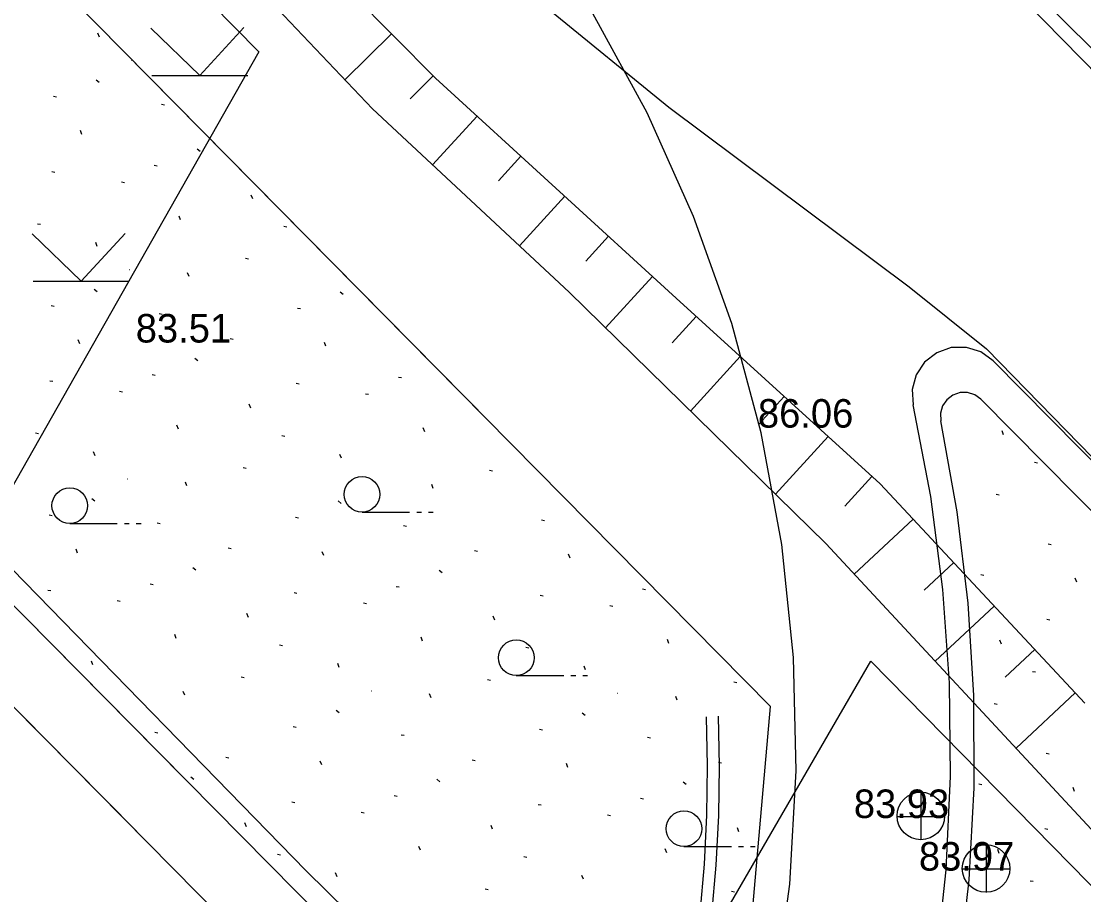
# Model space of a CAD drawing. Extents: x 412225 to 413380, y 4456471 to 4457189.
# Drawn here: x 412488.1 to 412532.83, y 4456813.88 to 4456850.62 of the extents above; entities that cross this region are included whole.
import ezdxf

# ---------------------------------------------------------------- set-up
doc = ezdxf.new("R2010")
doc.units = 0
for name, color, linetype in [('0_HALİHAZIR', 7, 'Continuous'), ('0_KADASTRO', 7, 'Continuous'), ('ADA_KOCEPHE', 7, 'Continuous'), ('ADA_ONCEPHE', 7, 'Continuous'), ('KALDIRIM', 7, 'Continuous'), ('Level 41', 7, 'Continuous'), ('Level 62', 7, 'Continuous')]:
    doc.layers.add(name, color=color, linetype=linetype)

msp = doc.modelspace()

# ---------------------------------------------------------------- linework, layer by layer
at = {"layer": '0_HALİHAZIR'}
for p, q in [((412495.622, 4456848.349), (412493.562, 4456850.339)), ((412495.622, 4456848.349), (412497.472, 4456850.358)), ((412503.688, 4456850.102), (412501.73, 4456848.159)), ((412493.602, 4456848.349), (412497.642, 4456848.348)), ((412505.449, 4456848.327), (412504.468, 4456847.354)), ((412507.29, 4456846.636), (412505.415, 4456844.584)), ((412509.135, 4456844.95), (412508.19, 4456843.915)), ((412510.981, 4456843.264), (412509.073, 4456841.175)), ((412490.621, 4456839.689), (412488.561, 4456841.679)), ((412490.621, 4456839.689), (412492.471, 4456841.699)), ((412512.827, 4456841.577), (412511.864, 4456840.524)), ((412514.673, 4456839.891), (412512.696, 4456837.727)), ((412488.601, 4456839.689), (412492.641, 4456839.689)), ((412516.52, 4456838.206), (412515.503, 4456837.09)), ((412518.368, 4456836.523), (412516.275, 4456834.224)), ((412520.216, 4456834.84), (412519.14, 4456833.657)), ((412522.065, 4456833.156), (412519.851, 4456830.725)), ((412523.913, 4456831.473), (412522.776, 4456830.224)), ((412502.448, 4456829.971), (412504.448, 4456829.971)), ((412504.748, 4456829.971), (412504.948, 4456829.971)), ((412505.248, 4456829.971), (412505.448, 4456829.971)), ((412490.144, 4456829.495), (412492.144, 4456829.495)), ((412492.444, 4456829.495), (412492.644, 4456829.495)), ((412492.944, 4456829.495), (412493.144, 4456829.495)), ((412525.646, 4456829.673), (412523.17, 4456827.361)), ((412527.352, 4456827.846), (412526.113, 4456826.688)), ((412529.059, 4456826.018), (412526.575, 4456823.699)), ((412530.765, 4456824.191), (412529.521, 4456823.03)), ((412508.942, 4456823.097), (412510.942, 4456823.097)), ((412511.242, 4456823.097), (412511.442, 4456823.097)), ((412511.742, 4456823.097), (412511.942, 4456823.097)), ((412532.471, 4456822.364), (412529.98, 4456820.038)), ((412525.989, 4456816.183), (412525.989, 4456818.183)), ((412524.969, 4456817.173), (412526.969, 4456817.173)), ((412516, 4456815.903), (412518, 4456815.902)), ((412518.3, 4456815.902), (412518.5, 4456815.902)), ((412518.8, 4456815.902), (412519, 4456815.902)), ((412528.734, 4456813.971), (412528.734, 4456815.971)), ((412527.714, 4456814.962), (412529.714, 4456814.961))]:
    msp.add_line(p, q, dxfattribs=at)
for points in [[(412283.985, 4457100.322), (412303.353, 4457080.961), (412332.911, 4457051.149), (412362.488, 4457021.336), (412400.253, 4456983.455), (412425.306, 4456957.949), (412451.956, 4456931.175), (412483.613, 4456899.459), (412507.045, 4456875.463), (412533.953, 4456848.693), (412570.746, 4456810.938), (412594.382, 4456786.967), (412618.72, 4456762.275), (412633.267, 4456747.178), (412636.335, 4456744.215)], [(412635.095, 4456744.706), (412621.293, 4456758.968), (412594.514, 4456786.189), (412564.28, 4456816.959), (412527.989, 4456853.886), (412497.963, 4456883.985), (412468.818, 4456913.357), (412423.738, 4456958.933), (412408.728, 4456974.086)], [(412461.571, 4456883.628), (412465.366, 4456883.75), (412468.462, 4456882.217), (412474.258, 4456878.127), (412489.749, 4456864.153), (412505.547, 4456848.228), (412515.676, 4456838.974), (412524.256, 4456831.161), (412532.872, 4456821.935)], [(412533.164, 4456816.614), (412521.975, 4456828.646), (412511.169, 4456839.221), (412502.887, 4456846.939), (412494.891, 4456855.369), (412485.404, 4456864.533), (412471.618, 4456876.544), (412465.786, 4456880.863), (412463.181, 4456882.534), (412461.571, 4456883.628)], [(412532.886, 4456773.972), (412532.31, 4456774.062), (412531.793, 4456774.564), (412531.273, 4456775.296), (412528.663, 4456779.548), (412524.693, 4456785.735), (412521.094, 4456791.304), (412516.782, 4456797.322), (412512.918, 4456801.901), (412508.059, 4456807.056), (412500.088, 4456814.895), (412487.722, 4456827.567), (412472.464, 4456842.514), (412454.647, 4456860.416), (412450.212, 4456864.756)], [(412505.182, 4456855.321), (412515.363, 4456847.006), (412525.484, 4456839.445), (412528.743, 4456836.847), (412540.992, 4456824.288)]]:
    msp.add_lwpolyline(points, dxfattribs=at)
for centre, radius in [((412502.448, 4456830.721), 0.75), ((412490.144, 4456830.245), 0.75), ((412508.942, 4456823.847), 0.75), ((412525.974, 4456817.191), 1), ((412516, 4456816.653), 0.75), ((412528.719, 4456814.98), 1)]:
    msp.add_circle(centre, radius, dxfattribs=at)
at = {"layer": '0_KADASTRO'}
msp.add_lwpolyline([(412245.621, 4457084.985), (412262.788, 4457087.767), (412498.109, 4456849.333), (412486.377, 4456828.685), (412245.456, 4457070.818)], dxfattribs=at)
msp.add_lwpolyline([(412511.64, 4456802.61), (412523.869, 4456823.705), (412617.056, 4456728.859), (412543.593, 4456703.12), (412527.466, 4456778.138), (412524.42, 4456784.89), (412522.24, 4456788.56), (412519.52, 4456792.85), (412512.99, 4456801.24)], close=True, dxfattribs=at)
at = {"layer": 'ADA_KOCEPHE'}
for p, q in [((412299.933, 4457044.174), (412519.643, 4456821.8)), ((412299.933, 4457044.174), (412507.885, 4456833.7)), ((412494.937, 4456818.806), (412285.694, 4457030.12)), ((412511.712, 4456801.864), (412285.694, 4457030.12))]:
    msp.add_line(p, q, dxfattribs=at)
at = {"layer": 'ADA_ONCEPHE'}
for p, q in [((412517.496, 4456819.294), (412517.449, 4456821.382)), ((412518.104, 4456804.245), (412519.643, 4456821.8)), ((412516.996, 4456819.292), (412516.95, 4456821.362)), ((412516.966, 4456817.222), (412516.996, 4456819.292)), ((412517.466, 4456817.206), (412517.496, 4456819.294)), ((412516.86, 4456815.155), (412516.966, 4456817.222)), ((412517.359, 4456815.12), (412517.466, 4456817.206)), ((412516.677, 4456813.093), (412516.86, 4456815.155)), ((412517.174, 4456813.04), (412517.359, 4456815.12))]:
    msp.add_line(p, q, dxfattribs=at)
at = {"layer": 'KALDIRIM'}
for p, q in [((412509.598, 4456799.736), (412281.429, 4457030.164)), ((412528.505, 4456834.72), (412551.839, 4456811.132))]:
    msp.add_line(p, q, dxfattribs=at)
for points in [[(412492.963, 4456816.536), (412269.398, 4457042.314)], [(412528.505, 4456834.72), (412528.247, 4456834.908), (412527.942, 4456835.005), (412527.623, 4456835.002), (412527.321, 4456834.897), (412527.067, 4456834.703), (412526.888, 4456834.439), (412526.8, 4456834.132), (412526.815, 4456833.812)], [(412526.055, 4456803.033), (412526.925, 4456806.817), (412527.576, 4456810.644), (412528.006, 4456814.502), (412528.213, 4456818.379), (412528.198, 4456822.261), (412527.959, 4456826.136), (412527.497, 4456829.991), (412526.815, 4456833.812)]]:
    msp.add_lwpolyline(points, dxfattribs=at)
at = {"layer": 'Level 41'}
for p, q in [((412491.392, 4456849.959), (412491.33, 4456850.121)), ((412491.392, 4456849.959), (412491.33, 4456850.121)), ((412492.74, 4456848.982), (412492.749, 4456848.98)), ((412492.74, 4456848.982), (412492.749, 4456848.98)), ((412491.256, 4456848.158), (412491.383, 4456848.058)), ((412491.256, 4456848.158), (412491.383, 4456848.058)), ((412489.456, 4456847.472), (412489.582, 4456847.446)), ((412489.456, 4456847.472), (412489.582, 4456847.446)), ((412494.001, 4456847.131), (412494.127, 4456847.107)), ((412494.001, 4456847.131), (412494.127, 4456847.107)), ((412490.653, 4456845.862), (412490.589, 4456846.025)), ((412490.653, 4456845.862), (412490.589, 4456846.025)), ((412495.506, 4456845.254), (412495.632, 4456845.153)), ((412495.506, 4456845.254), (412495.632, 4456845.153)), ((412489.396, 4456844.306), (412489.522, 4456844.282)), ((412489.396, 4456844.306), (412489.522, 4456844.282)), ((412493.704, 4456844.566), (412493.83, 4456844.542)), ((412493.704, 4456844.566), (412493.83, 4456844.542)), ((412492.321, 4456843.867), (412492.447, 4456843.841)), ((412492.321, 4456843.867), (412492.447, 4456843.841)), ((412497.85, 4456843.151), (412497.785, 4456843.314)), ((412497.85, 4456843.151), (412497.785, 4456843.314)), ((412494.809, 4456842.267), (412494.746, 4456842.431)), ((412494.809, 4456842.267), (412494.746, 4456842.431)), ((412488.789, 4456842.108), (412488.915, 4456842.084)), ((412488.789, 4456842.108), (412488.915, 4456842.084)), ((412499.157, 4456842.002), (412499.283, 4456841.977)), ((412499.157, 4456842.002), (412499.283, 4456841.977)), ((412491.302, 4456841.154), (412491.24, 4456841.316)), ((412491.302, 4456841.154), (412491.24, 4456841.316)), ((412497.539, 4456840.651), (412497.665, 4456840.626)), ((412497.539, 4456840.651), (412497.665, 4456840.626)), ((412492.65, 4456840.176), (412492.658, 4456840.175)), ((412492.65, 4456840.176), (412492.658, 4456840.175)), ((412495.167, 4456839.881), (412495.103, 4456840.044)), ((412495.167, 4456839.881), (412495.103, 4456840.044)), ((412491.166, 4456839.353), (412491.293, 4456839.253)), ((412491.166, 4456839.353), (412491.293, 4456839.253)), ((412501.534, 4456839.247), (412501.66, 4456839.147)), ((412501.534, 4456839.247), (412501.66, 4456839.147)), ((412489.366, 4456838.666), (412489.492, 4456838.641)), ((412489.366, 4456838.666), (412489.492, 4456838.641)), ((412499.733, 4456838.56), (412499.859, 4456838.535)), ((412499.733, 4456838.56), (412499.859, 4456838.535)), ((412493.91, 4456838.326), (412494.036, 4456838.301)), ((412493.91, 4456838.326), (412494.036, 4456838.301)), ((412490.562, 4456837.056), (412490.499, 4456837.219)), ((412490.562, 4456837.056), (412490.499, 4456837.219)), ((412496.899, 4456837.271), (412497.024, 4456837.245)), ((412496.899, 4456837.271), (412497.024, 4456837.245)), ((412500.93, 4456836.95), (412500.867, 4456837.113)), ((412500.93, 4456836.95), (412500.867, 4456837.113)), ((412495.416, 4456836.448), (412495.542, 4456836.347)), ((412495.416, 4456836.448), (412495.542, 4456836.347)), ((412493.614, 4456835.761), (412493.74, 4456835.736)), ((412493.614, 4456835.761), (412493.74, 4456835.736)), ((412489.306, 4456835.501), (412489.432, 4456835.476)), ((412489.306, 4456835.501), (412489.432, 4456835.476)), ((412499.674, 4456835.395), (412499.8, 4456835.37)), ((412499.674, 4456835.395), (412499.8, 4456835.37)), ((412503.981, 4456835.655), (412504.108, 4456835.63)), ((412503.981, 4456835.655), (412504.108, 4456835.63)), ((412492.231, 4456835.061), (412492.357, 4456835.035)), ((412492.231, 4456835.061), (412492.357, 4456835.035)), ((412502.599, 4456834.955), (412502.725, 4456834.929)), ((412502.599, 4456834.955), (412502.725, 4456834.929)), ((412497.76, 4456834.345), (412497.695, 4456834.508)), ((412497.76, 4456834.345), (412497.695, 4456834.508)), ((412494.719, 4456833.462), (412494.656, 4456833.626)), ((412494.719, 4456833.462), (412494.656, 4456833.626)), ((412505.087, 4456833.356), (412505.023, 4456833.52)), ((412505.087, 4456833.356), (412505.023, 4456833.52)), ((412488.699, 4456833.303), (412488.825, 4456833.278)), ((412488.699, 4456833.303), (412488.825, 4456833.278)), ((412499.067, 4456833.197), (412499.193, 4456833.172)), ((412499.067, 4456833.197), (412499.193, 4456833.172)), ((412529.454, 4456833.227), (412529.39, 4456833.389)), ((412529.454, 4456833.227), (412529.39, 4456833.389)), ((412491.212, 4456832.348), (412491.15, 4456832.51)), ((412491.212, 4456832.348), (412491.15, 4456832.51)), ((412501.579, 4456832.242), (412501.517, 4456832.404)), ((412501.579, 4456832.242), (412501.517, 4456832.404)), ((412497.449, 4456831.846), (412497.575, 4456831.82)), ((412497.449, 4456831.846), (412497.575, 4456831.82)), ((412507.817, 4456831.74), (412507.943, 4456831.714)), ((412507.817, 4456831.74), (412507.943, 4456831.714)), ((412530.761, 4456832.078), (412530.887, 4456832.053)), ((412530.761, 4456832.078), (412530.887, 4456832.053)), ((412492.56, 4456831.371), (412492.568, 4456831.369)), ((412492.56, 4456831.371), (412492.568, 4456831.369)), ((412495.077, 4456831.075), (412495.013, 4456831.238)), ((412495.077, 4456831.075), (412495.013, 4456831.238)), ((412502.927, 4456831.265), (412502.936, 4456831.263)), ((412502.927, 4456831.265), (412502.936, 4456831.263)), ((412505.444, 4456830.969), (412505.381, 4456831.132)), ((412505.444, 4456830.969), (412505.381, 4456831.132)), ((412491.076, 4456830.547), (412491.202, 4456830.447)), ((412491.076, 4456830.547), (412491.202, 4456830.447)), ((412501.444, 4456830.441), (412501.57, 4456830.341)), ((412501.444, 4456830.441), (412501.57, 4456830.341)), ((412529.144, 4456830.727), (412529.27, 4456830.701)), ((412529.144, 4456830.727), (412529.27, 4456830.701)), ((412489.275, 4456829.861), (412489.402, 4456829.835)), ((412489.275, 4456829.861), (412489.402, 4456829.835)), ((412493.82, 4456829.52), (412493.946, 4456829.495)), ((412493.82, 4456829.52), (412493.946, 4456829.495)), ((412499.643, 4456829.755), (412499.769, 4456829.729)), ((412499.643, 4456829.755), (412499.769, 4456829.729)), ((412504.188, 4456829.414), (412504.314, 4456829.389)), ((412504.188, 4456829.414), (412504.314, 4456829.389)), ((412510.01, 4456829.649), (412510.136, 4456829.623)), ((412510.01, 4456829.649), (412510.136, 4456829.623)), ((412531.338, 4456828.636), (412531.464, 4456828.61)), ((412531.338, 4456828.636), (412531.464, 4456828.61)), ((412490.472, 4456828.251), (412490.409, 4456828.414)), ((412490.472, 4456828.251), (412490.409, 4456828.414)), ((412496.809, 4456828.465), (412496.934, 4456828.439)), ((412496.809, 4456828.465), (412496.934, 4456828.439)), ((412500.84, 4456828.145), (412500.776, 4456828.307)), ((412500.84, 4456828.145), (412500.776, 4456828.307)), ((412507.177, 4456828.359), (412507.302, 4456828.333)), ((412507.177, 4456828.359), (412507.302, 4456828.333)), ((412511.207, 4456828.038), (412511.144, 4456828.201)), ((412511.207, 4456828.038), (412511.144, 4456828.201)), ((412495.326, 4456827.643), (412495.452, 4456827.542)), ((412495.326, 4456827.643), (412495.452, 4456827.542)), ((412505.693, 4456827.536), (412505.819, 4456827.436)), ((412505.693, 4456827.536), (412505.819, 4456827.436)), ((412528.504, 4456827.346), (412528.629, 4456827.321)), ((412528.504, 4456827.346), (412528.629, 4456827.321)), ((412532.535, 4456827.026), (412532.471, 4456827.189)), ((412532.535, 4456827.026), (412532.471, 4456827.189)), ((412493.524, 4456826.955), (412493.65, 4456826.931)), ((412493.524, 4456826.955), (412493.65, 4456826.931)), ((412503.891, 4456826.849), (412504.017, 4456826.824)), ((412503.891, 4456826.849), (412504.017, 4456826.824)), ((412514.259, 4456826.743), (412514.385, 4456826.718)), ((412514.259, 4456826.743), (412514.385, 4456826.718)), ((412489.216, 4456826.695), (412489.342, 4456826.671)), ((412489.216, 4456826.695), (412489.342, 4456826.671)), ((412499.584, 4456826.589), (412499.71, 4456826.565)), ((412499.584, 4456826.589), (412499.71, 4456826.565)), ((412509.951, 4456826.483), (412510.077, 4456826.458)), ((412509.951, 4456826.483), (412510.077, 4456826.458)), ((412492.141, 4456826.256), (412492.267, 4456826.23)), ((412492.141, 4456826.256), (412492.267, 4456826.23)), ((412502.508, 4456826.15), (412502.634, 4456826.124)), ((412502.508, 4456826.15), (412502.634, 4456826.124)), ((412512.876, 4456826.043), (412513.002, 4456826.018)), ((412512.876, 4456826.043), (412513.002, 4456826.018)), ((412497.669, 4456825.54), (412497.605, 4456825.703)), ((412497.669, 4456825.54), (412497.605, 4456825.703)), ((412508.037, 4456825.434), (412507.973, 4456825.597)), ((412508.037, 4456825.434), (412507.973, 4456825.597)), ((412531.278, 4456825.47), (412531.404, 4456825.446)), ((412531.278, 4456825.47), (412531.404, 4456825.446)), ((412494.629, 4456824.656), (412494.566, 4456824.82)), ((412494.629, 4456824.656), (412494.566, 4456824.82)), ((412504.997, 4456824.55), (412504.933, 4456824.714)), ((412504.997, 4456824.55), (412504.933, 4456824.714)), ((412515.364, 4456824.444), (412515.301, 4456824.608)), ((412515.364, 4456824.444), (412515.301, 4456824.608)), ((412529.364, 4456824.421), (412529.3, 4456824.584)), ((412529.364, 4456824.421), (412529.3, 4456824.584)), ((412498.977, 4456824.391), (412499.103, 4456824.366)), ((412498.977, 4456824.391), (412499.103, 4456824.366)), ((412509.344, 4456824.285), (412509.47, 4456824.26)), ((412509.344, 4456824.285), (412509.47, 4456824.26)), ((412491.122, 4456823.543), (412491.06, 4456823.705)), ((412491.122, 4456823.543), (412491.06, 4456823.705)), ((412501.489, 4456823.437), (412501.427, 4456823.599)), ((412501.489, 4456823.437), (412501.427, 4456823.599)), ((412511.857, 4456823.331), (412511.794, 4456823.493)), ((412511.857, 4456823.331), (412511.794, 4456823.493)), ((412530.671, 4456823.272), (412530.797, 4456823.248)), ((412530.671, 4456823.272), (412530.797, 4456823.248)), ((412497.359, 4456823.04), (412497.485, 4456823.014)), ((412497.359, 4456823.04), (412497.485, 4456823.014)), ((412507.726, 4456822.934), (412507.853, 4456822.908)), ((412507.726, 4456822.934), (412507.853, 4456822.908)), ((412518.094, 4456822.828), (412518.22, 4456822.802)), ((412518.094, 4456822.828), (412518.22, 4456822.802)), ((412492.47, 4456822.565), (412492.478, 4456822.563)), ((412492.47, 4456822.565), (412492.478, 4456822.563)), ((412494.986, 4456822.27), (412494.923, 4456822.433)), ((412494.986, 4456822.27), (412494.923, 4456822.433)), ((412502.837, 4456822.459), (412502.846, 4456822.457)), ((412502.837, 4456822.459), (412502.846, 4456822.457)), ((412505.354, 4456822.164), (412505.291, 4456822.327)), ((412505.354, 4456822.164), (412505.291, 4456822.327)), ((412513.205, 4456822.353), (412513.213, 4456822.351)), ((412513.205, 4456822.353), (412513.213, 4456822.351)), ((412515.721, 4456822.058), (412515.658, 4456822.221)), ((412515.721, 4456822.058), (412515.658, 4456822.221)), ((412529.054, 4456821.921), (412529.18, 4456821.896)), ((412529.054, 4456821.921), (412529.18, 4456821.896)), ((412501.354, 4456821.635), (412501.48, 4456821.536)), ((412501.354, 4456821.635), (412501.48, 4456821.536)), ((412511.721, 4456821.529), (412511.847, 4456821.43)), ((412511.721, 4456821.529), (412511.847, 4456821.43)), ((412499.553, 4456820.949), (412499.679, 4456820.923)), ((412499.553, 4456820.949), (412499.679, 4456820.923)), ((412493.73, 4456820.715), (412493.856, 4456820.69)), ((412493.73, 4456820.715), (412493.856, 4456820.69)), ((412504.098, 4456820.609), (412504.224, 4456820.584)), ((412504.098, 4456820.609), (412504.224, 4456820.584)), ((412509.92, 4456820.843), (412510.046, 4456820.817)), ((412509.92, 4456820.843), (412510.046, 4456820.817)), ((412514.465, 4456820.502), (412514.591, 4456820.478)), ((412514.465, 4456820.502), (412514.591, 4456820.478)), ((412496.719, 4456819.66), (412496.844, 4456819.634)), ((412496.719, 4456819.66), (412496.844, 4456819.634)), ((412531.248, 4456819.83), (412531.374, 4456819.805)), ((412531.248, 4456819.83), (412531.374, 4456819.805)), ((412500.75, 4456819.339), (412500.686, 4456819.502)), ((412500.75, 4456819.339), (412500.686, 4456819.502)), ((412507.087, 4456819.554), (412507.212, 4456819.528)), ((412507.087, 4456819.554), (412507.212, 4456819.528)), ((412511.117, 4456819.233), (412511.054, 4456819.396)), ((412511.117, 4456819.233), (412511.054, 4456819.396)), ((412517.454, 4456819.448), (412517.579, 4456819.422)), ((412517.454, 4456819.448), (412517.579, 4456819.422)), ((412495.236, 4456818.837), (412495.362, 4456818.736)), ((412495.236, 4456818.837), (412495.362, 4456818.736)), ((412505.603, 4456818.731), (412505.729, 4456818.63)), ((412505.603, 4456818.731), (412505.729, 4456818.63)), ((412515.97, 4456818.625), (412516.097, 4456818.524)), ((412515.97, 4456818.625), (412516.097, 4456818.524)), ((412528.414, 4456818.541), (412528.539, 4456818.515)), ((412528.414, 4456818.541), (412528.539, 4456818.515)), ((412532.444, 4456818.22), (412532.381, 4456818.383)), ((412532.444, 4456818.22), (412532.381, 4456818.383)), ((412503.801, 4456818.044), (412503.927, 4456818.019)), ((412503.801, 4456818.044), (412503.927, 4456818.019)), ((412514.169, 4456817.938), (412514.295, 4456817.913)), ((412514.169, 4456817.938), (412514.295, 4456817.913)), ((412499.493, 4456817.784), (412499.619, 4456817.759)), ((412499.493, 4456817.784), (412499.619, 4456817.759)), ((412502.418, 4456817.344), (412502.544, 4456817.318)), ((412502.418, 4456817.344), (412502.544, 4456817.318)), ((412509.861, 4456817.678), (412509.987, 4456817.653)), ((412509.861, 4456817.678), (412509.987, 4456817.653)), ((412497.579, 4456816.734), (412497.515, 4456816.897)), ((412497.579, 4456816.734), (412497.515, 4456816.897)), ((412512.786, 4456817.238), (412512.912, 4456817.212)), ((412512.786, 4456817.238), (412512.912, 4456817.212)), ((412507.947, 4456816.628), (412507.883, 4456816.791)), ((412507.947, 4456816.628), (412507.883, 4456816.791)), ((412518.314, 4456816.522), (412518.25, 4456816.685)), ((412518.314, 4456816.522), (412518.25, 4456816.685)), ((412531.188, 4456816.665), (412531.314, 4456816.64)), ((412531.188, 4456816.665), (412531.314, 4456816.64)), ((412498.886, 4456815.586), (412499.012, 4456815.561)), ((412498.886, 4456815.586), (412499.012, 4456815.561)), ((412504.906, 4456815.745), (412504.843, 4456815.909)), ((412504.906, 4456815.745), (412504.843, 4456815.909)), ((412515.274, 4456815.639), (412515.211, 4456815.802)), ((412515.274, 4456815.639), (412515.211, 4456815.802)), ((412529.274, 4456815.615), (412529.21, 4456815.778)), ((412529.274, 4456815.615), (412529.21, 4456815.778)), ((412509.254, 4456815.48), (412509.38, 4456815.455)), ((412509.254, 4456815.48), (412509.38, 4456815.455)), ((412501.399, 4456814.631), (412501.337, 4456814.793)), ((412501.399, 4456814.631), (412501.337, 4456814.793)), ((412511.767, 4456814.525), (412511.704, 4456814.687)), ((412511.767, 4456814.525), (412511.704, 4456814.687)), ((412530.581, 4456814.467), (412530.707, 4456814.442)), ((412530.581, 4456814.467), (412530.707, 4456814.442)), ((412507.636, 4456814.129), (412507.762, 4456814.103)), ((412507.636, 4456814.129), (412507.762, 4456814.103)), ((412518.004, 4456814.022), (412518.13, 4456813.997)), ((412518.004, 4456814.022), (412518.13, 4456813.997))]:
    msp.add_line(p, q, dxfattribs=at)
at = {"layer": 'Level 62'}
msp.add_line((412529.02, 4456836.332), (412553.204, 4456811.885), dxfattribs=at)
for points in [[(412518.798, 4456804.923), (412519.816, 4456809.588), (412520.46, 4456814.319), (412520.726, 4456819.086), (412520.613, 4456823.859), (412520.12, 4456828.608), (412519.251, 4456833.303), (412518.011, 4456837.914), (412516.409, 4456842.412), (412514.454, 4456846.768), (412512.159, 4456850.955), (412509.538, 4456854.946), (412506.609, 4456858.716), (412503.388, 4456862.241)], [(412529.02, 4456836.332), (412528.501, 4456836.71), (412527.888, 4456836.904), (412527.246, 4456836.894), (412526.64, 4456836.681), (412526.133, 4456836.287), (412525.777, 4456835.752), (412525.609, 4456835.132), (412525.646, 4456834.491)], [(412525.088, 4456803.285), (412525.967, 4456807.123), (412526.617, 4456811.007), (412527.036, 4456814.922), (412527.223, 4456818.855), (412527.177, 4456822.792), (412526.898, 4456826.72), (412526.387, 4456830.624), (412525.646, 4456834.491)]]:
    msp.add_lwpolyline(points, dxfattribs=at)

# ---------------------------------------------------------------- texts
at = {"layer": '0_HALİHAZIR'}
for s, p in [('83.51', (412492.921, 4456837.108)), ('86.06', (412519.114, 4456833.528)), ('83.93', (412523.152, 4456817.103)), ('83.97', (412525.892, 4456814.892))]:
    msp.add_text(s, height=1.2, dxfattribs=at).set_placement(p)

doc.saveas('drawing.dxf')
